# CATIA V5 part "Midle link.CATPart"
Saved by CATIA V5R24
Part number: Midle link
Bounding box of the stored display mesh (mm): x -4.5 to 4.5, y -22.4 to -16.6, z 0 to 2.8
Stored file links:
  C:\Users\Jules\Documents\ECL\Watch\Midle link.CATPart
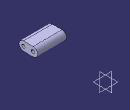
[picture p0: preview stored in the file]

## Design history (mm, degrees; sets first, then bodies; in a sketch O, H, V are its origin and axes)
Body1 (main body)
  Sketch1 on yz-plane, origin (0, 0, 0), H (0, 1, 0), V (0, 0, 1)
    line L1 (-21, 2.8) -> (-18, 2.8)
    arc A1 centre (-18, 1.4) radius 1.4 from (-18, 2.8) to (-18, 0) cw
    point P3 (-18, 1.4)
    point P4 (-18, 0)
    line L2 (-18, 0) -> (-21, 0)
    arc A2 centre (-21, 1.4) radius 1.4 from (-21, 0) to (-21, 2.8) cw
    circle A3 centre (-18, 1.4) radius 0.55
    circle A4 centre (-21, 1.4) radius 0.55
    radius A1 = 1.4
    length L2 = 3
    distance P3 V = 18
    radius A3 = 0.55
    radius A4 = 0.55
    horizontal: L1 H
    coincidence: P4 H
    tangency: A1 L1, L2 A1, A2 L1, A2 L2
  Pad1: profile Sketch1, direction (1, 0, 0), length 4.5, mirrored extent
